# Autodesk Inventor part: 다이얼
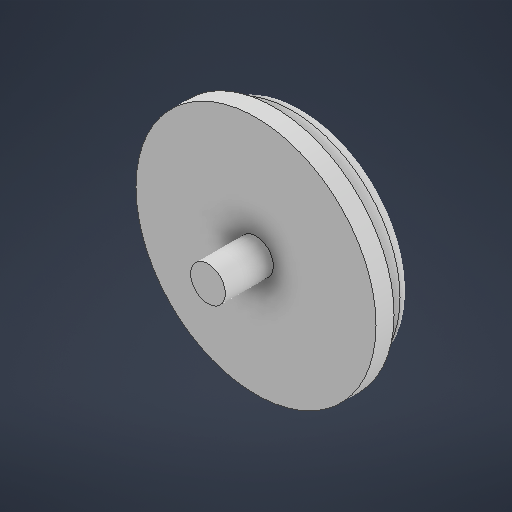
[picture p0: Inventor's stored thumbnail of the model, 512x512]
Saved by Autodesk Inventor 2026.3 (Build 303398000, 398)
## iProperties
Created: 2026-08
Part Number: 다이얼
Material: 일반
Document SubType Name: Modeling
Designer: chang
Density: 1 g/cm^3
Appearance: 기본값
Author: chang
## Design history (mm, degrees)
sketch "스케치1"
  geometry: L1 (0, 0)-(19.678, 0); L2 (0, 0)-(0, 19.678); L3 (0, 0)-(-19.678, 0); L4 (0, 0)-(0, -19.678); C1 r 18 at (0, 0); C2 r 3 at (0, 13.5); C3 r 3 at (9.546, 9.546) reference; C4 r 18 at (0, 0); C5 r 3 at (-13.5, 0); C6 r 3 at (-9.546, 9.546); C7 r 18 at (0, 0); C8 r 3 at (0, -13.5); C9 r 3 at (-9.546, -9.546); C10 r 18 at (0, 0); C11 r 3 at (13.5, 0) reference; C12 r 3 at (9.546, -9.546); 1 further point
  constraints: 12 centre point, 8 end point, 1 coincident, 1 horizontal, 37 other
  dimensions: "d0" = 36 diameter of C1; "d8" = 360 deg dimension on point (0, 0) C2.centre (derived)
extrude "돌출1" new body sketch "스케치1" distance "d10" = 5; taper "d11" = 0 deg
sketch "스케치2"
  geometry: C1 r 20 at (0, 0); 1 further point
  constraints: 1 centre point, 1 coincident
  dimensions: "d12" = 40 diameter of C1
extrude "돌출2" join sketch "스케치2" distance "d13" = 3; taper "d14" = 0 deg
feature "면 모깎기1" dims "d15" = 0.931
fillet "모깎기1" dims "d16" = 2
sketch "스케치3"
  geometry: C1 r 2.9 at (0, 0); 1 further point
  constraints: 1 centre point, 1 coincident
  dimensions: "d17" = 5.8 diameter of C1
extrude "돌출3" join sketch "스케치3" distance "d18" = 8; taper "d19" = 0 deg
node "솔리드1"
node "스케치 - 원형 패턴1" dims "d8" = 360 deg (derived)
other parameters: "d3" = 45 deg
